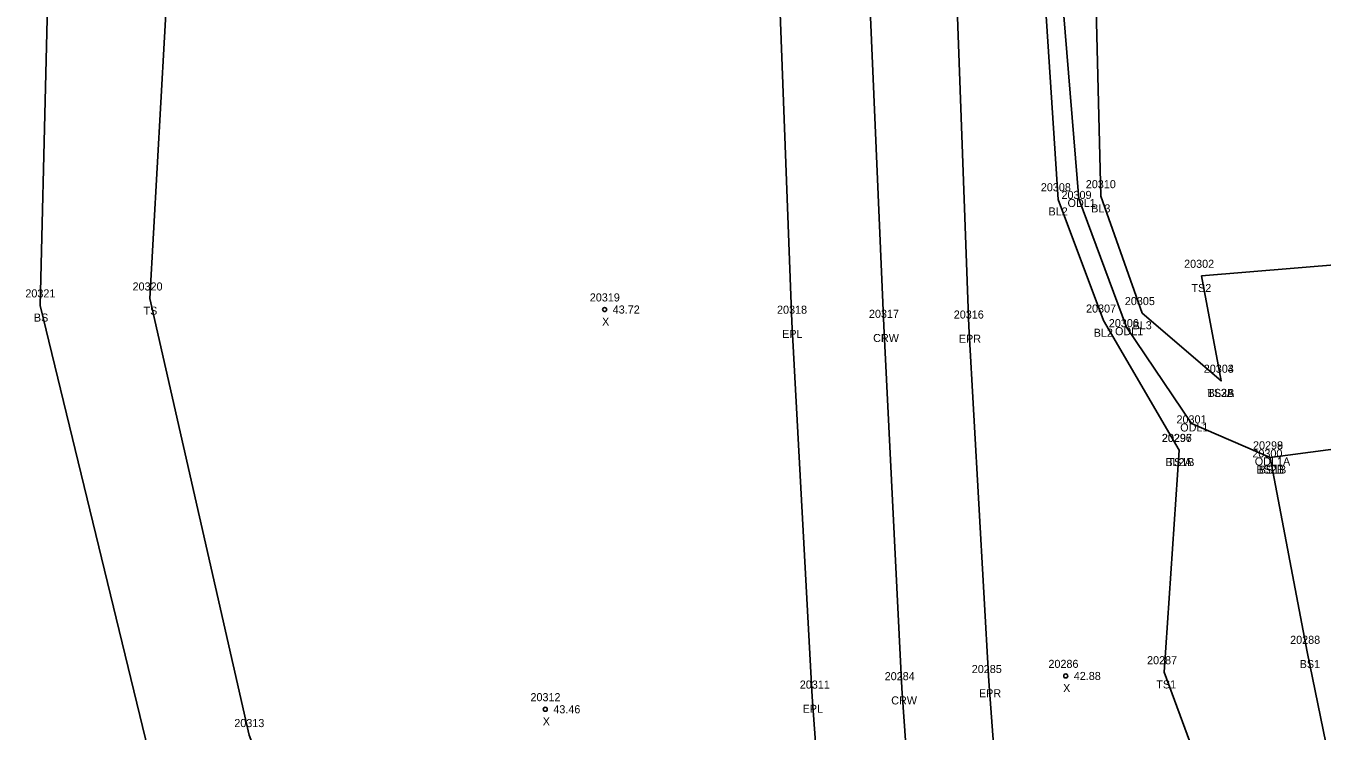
# Model space of a CAD drawing. Extents: x 2445178 to 2446260, y 791158 to 792318.
# Drawn here: x 2445586 to 2445746.6, y 791982.9 to 792070.4 of the extents above; entities that cross this region are included whole.
import ezdxf

# ---------------------------------------------------------------- set-up
doc = ezdxf.new("R2010")
doc.units = 0
for name, color, linetype in [('RD_DTM_BkLn1', 7, 'Continuous'), ('RD_DTM_BkLn2', 7, 'Continuous'), ('RD_EX_H2O', 7, 'Continuous'), ('RD_EX_H2O_txCode', 7, 'Continuous'), ('RD_EX_Road', 7, 'Continuous'), ('RD_EX_Road_txCode', 7, 'Continuous'), ('RD_Sketch8', 7, 'Continuous'), ('RD_SMD_Locator', 7, 'Continuous'), ('RD_SMD_Misc', 7, 'Continuous')]:
    doc.layers.add(name, color=color, linetype=linetype)

msp = doc.modelspace()

# ---------------------------------------------------------------- linework, layer by layer
at = {"layer": 'RD_DTM_BkLn1'}
for points in [[(2445728.86, 792017.77), (2445719.5, 792033.81), (2445713.9, 792048.85), (2445711.05, 792092.47), (2445709, 792203.69), (2445705.99, 792302.65)], [(2445734.09, 792026.35), (2445724.31, 792034.74), (2445719.18, 792049.23), (2445718.08, 792092.37), (2445714.21, 792204.46), (2445712.52, 792303.23)], [(2445710.31, 791817.61), (2445703.89, 791871.62), (2445699.09, 791922.95), (2445694.51, 791988.23), (2445692.28, 792033.16), (2445689.82, 792090.63), (2445687.08, 792198.77), (2445684.85, 792300.91)]]:
    msp.add_lwpolyline(points, dxfattribs=at)
at = {"layer": 'RD_DTM_BkLn2'}
for points in [[(2445721.97, 791816.74), (2445696.27, 791809.15), (2445685.63, 791803.83), (2445656.7, 791816.36), (2445642.32, 791839.59), (2445634.31, 791862.06), (2445625.81, 791909.02), (2445601.16, 791980.42), (2445587.75, 792035.69), (2445589.15, 792093.24), (2445629.12, 792201.55), (2445634.25, 792303.36)], [(2445696.53, 791819.13), (2445688.31, 791813.55), (2445675.47, 791816.83), (2445662.11, 791825.5), (2445653.3, 791862.54), (2445641.21, 791910.45), (2445613.64, 791982.42), (2445601.35, 792036.55), (2445604.5, 792093.32), (2445645.58, 792199.83), (2445656.44, 792300.62)], [(2445856.1, 792061.09), (2445789.75, 792048.22), (2445755.11, 792041.33), (2445731.65, 792039.36), (2445734.09, 792026.35)], [(2445864.47, 792009.75), (2445791.07, 792023.6), (2445740.15, 792016.85)], [(2445723.15, 791827.97), (2445742.38, 791824.93), (2445764.31, 791858.33), (2445764.27, 791888.69), (2445750.79, 791925.83), (2445727.01, 791990.21), (2445728.86, 792017.77)], [(2445721.97, 791816.74), (2445749.98, 791821.69), (2445763.92, 791830.66), (2445773.82, 791855.25), (2445775.82, 791885.45), (2445758.38, 791926.24), (2445744.75, 791992.74), (2445740.15, 792016.85)]]:
    msp.add_lwpolyline(points, dxfattribs=at)
at = {"layer": 'RD_EX_H2O'}
msp.add_lwpolyline([(2445740.15, 792016.85), (2445730.42, 792021.07), (2445722.34, 792033), (2445716.46, 792048.9), (2445712.84, 792092.81), (2445710.99, 792204.22), (2445707.93, 792302.49)], dxfattribs=at)
at = {"layer": 'RD_EX_Road'}
for points in [[(2445719.65, 791821.33), (2445720.29, 791823.76), (2445714.87, 791872.94), (2445710.18, 791923.37), (2445705.3, 791989.12), (2445702.81, 792033.07), (2445700.66, 792091.77), (2445697.78, 792201.78), (2445695.41, 792302.8)], [(2445699.57, 791813.34), (2445693.24, 791870.48), (2445688.14, 791921.92), (2445683.42, 791987.19), (2445680.88, 792033.67), (2445678.74, 792090.55), (2445675.91, 792199.23), (2445673.61, 792301.11)]]:
    msp.add_lwpolyline(points, dxfattribs=at)
at = {"layer": 'RD_SMD_Locator'}
for centre, radius in [((2445713.9, 792048.85), 0.001), ((2445716.46, 792048.9), 0.001), ((2445719.18, 792049.23), 0.001), ((2445731.65, 792039.36), 0.001), ((2445587.75, 792035.69), 0.001), ((2445601.35, 792036.55), 0.001), ((2445657.69, 792035.19), 0.25), ((2445719.5, 792033.81), 0.001), ((2445724.31, 792034.74), 0.001), ((2445680.88, 792033.67), 0.001), ((2445692.28, 792033.16), 0.001), ((2445702.81, 792033.07), 0.001), ((2445722.34, 792033), 0.001), ((2445734.09, 792026.35), 0.001), ((2445734.09, 792026.35), 0.001), ((2445730.42, 792021.07), 0.001), ((2445728.86, 792017.77), 0.001), ((2445728.86, 792017.77), 0.001), ((2445740.15, 792016.85), 0.001), ((2445740.15, 792016.85), 0.001), ((2445740.15, 792016.85), 0.001), ((2445744.75, 791992.74), 0.001), ((2445705.3, 791989.12), 0.001), ((2445714.82, 791989.76), 0.25), ((2445727.01, 791990.21), 0.001), ((2445683.42, 791987.19), 0.001), ((2445694.51, 791988.23), 0.001), ((2445650.33, 791985.63), 0.25)]:
    msp.add_circle(centre, radius, dxfattribs=at)

# ---------------------------------------------------------------- texts
at = {"layer": 'RD_EX_H2O_txCode'}
for s, p in [('20309', (2445714.3, 792048.9)), ('ODL1', (2445715.05, 792047.9)), ('20306', (2445720.16, 792033)), ('ODL1', (2445720.93, 792032)), ('20301', (2445728.55, 792021.07)), ('ODL1', (2445729.01, 792020.07)), ('20300', (2445737.95, 792016.85)), ('ODL1A', (2445738.25, 792015.85))]:
    msp.add_text(s, height=1, dxfattribs=at).set_placement(p)
at = {"layer": 'RD_EX_Road_txCode'}
for s, p in [('20318', (2445679.05, 792034.67)), ('20316', (2445700.95, 792034.07)), ('EPL', (2445679.68, 792031.67)), ('EPR', (2445701.58, 792031.07)), ('20285', (2445703.18, 791990.12)), ('20311', (2445681.87, 791988.19)), ('EPR', (2445704.07, 791987.12)), ('EPL', (2445682.22, 791985.19))]:
    msp.add_text(s, height=1, dxfattribs=at).set_placement(p)
at = {"layer": 'RD_Sketch8'}
for s, p in [('20319', (2445655.85, 792036.19)), ('43.72', (2445658.69, 792034.69)), ('X', (2445657.37, 792033.19)), ('20286', (2445712.68, 791990.76)), ('42.88', (2445715.82, 791989.26)), ('20312', (2445648.5, 791986.63)), ('X', (2445714.5, 791987.76)), ('43.46', (2445651.33, 791985.13)), ('X', (2445650.02, 791983.63))]:
    msp.add_text(s, height=1, dxfattribs=at).set_placement(p)
at = {"layer": 'RD_SMD_Misc'}
for s, p in [('20308', (2445711.74, 792049.85)), ('20310', (2445717.31, 792050.23)), ('BL3', (2445717.98, 792047.23)), ('BL2', (2445712.69, 792046.85)), ('20302', (2445729.49, 792040.36)), ('20321', (2445585.91, 792036.69)), ('20320', (2445599.19, 792037.55)), ('TS2', (2445730.4, 792037.36)), ('TS', (2445600.55, 792034.55)), ('20307', (2445717.34, 792034.81)), ('20305', (2445722.15, 792035.74)), ('BS', (2445586.97, 792033.69)), ('20317', (2445690.44, 792034.16)), ('BL3', (2445723.1, 792032.74)), ('CRW', (2445690.96, 792031.16)), ('BL2', (2445718.29, 792031.81)), ('20303', (2445731.93, 792027.35)), ('20304', (2445731.93, 792027.35)), ('TS2B', (2445732.37, 792024.35)), ('BL3A', (2445732.4, 792024.35)), ('20296', (2445726.72, 792018.77)), ('20297', (2445726.75, 792018.77)), ('20298', (2445738.03, 792017.85)), ('20299', (2445738.03, 792017.85)), ('BL2A', (2445727.17, 792015.77)), ('TS1B', (2445727.43, 792015.77)), ('BS2B', (2445738.44, 792014.85)), ('BS1B', (2445738.73, 792014.85)), ('20288', (2445742.63, 791993.74)), ('20287', (2445724.9, 791991.21)), ('BS1', (2445743.81, 791990.74)), ('20284', (2445692.39, 791989.23)), ('TS1', (2445726.05, 791988.21)), ('CRW', (2445693.2, 791986.23)), ('20313', (2445611.8, 791983.42))]:
    msp.add_text(s, height=1, dxfattribs=at).set_placement(p)

doc.saveas('drawing.dxf')
